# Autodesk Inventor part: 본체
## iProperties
Company: 한국ATC센터
Created: 2014-10
Part Number: 본체
Document SubType Name: Modeling
Designer: 한국ATC센터
Density: 2.71 g/cm^3
Material: 용접된 알루미늄-6061
Mass: 3285.44 g
Surface Area: 2358.47 cm^2
Volume: 1212.34 cm^3
Author: KYOUNG IL JANG
